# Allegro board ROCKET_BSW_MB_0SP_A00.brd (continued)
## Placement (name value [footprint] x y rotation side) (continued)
U2601  NCT7718W-GP  [MSOP8-1H44]  93.66 67.01 180 bottom
U2701  ALC3234-CG-GP  [QFN48J6-G465H40]  140.48 89.78 180 bottom
U2901  2N7002KDW-GP  [SOT-363H44]  149.73 87.56 180 bottom
U3301  RTS5176E-GRT-GP  [QFN24-G2D5H40-U]  14.1 40.77 0 bottom
U3601  G524B2T11U-GP  [SOT-23-5H58]  21.78 54.6 0 bottom
U4001  APL3523AQBI-TRG-GP  [SON14J3020-G2610H32]  147.06 47.31 270 bottom
U4016  APL3523AQBI-TRG-GP  [SON14J3020-G2610H32]  45.31 12.12 270 bottom
U5501  RT9724GB-GP  [SOT-23-5H51]  66.68 80.65 90 bottom
U6301  KLMBG4GEND-B031-GP  [BGA153G115130-1H40]  105.26 93.07 90 bottom
U6901  LNG2DMTR-GP  [LGA12G2H40]  56.62 91.47 270 top
USB1  SKT-USB13-262-GP  [SKT-USB13-160161]  5.39 54.5 90 bottom
WLAN1  SKT-NGFF75P-142-GP-U  [NFSA0-S6705-TP20]  175.1 85.5 90 bottom
X1601  XTAL-19D2MHZ-21-GP  [OSC-3225-4P-4H32]  53.97 46.22 270 bottom
X1802  XTAL-32D768KHZ-6-GP  [SMD-OSC2H56]  50.15 50.11 180 bottom

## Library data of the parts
AFTP2901-AFTP2904 AFTP2906-AFTP2909 AFTP3401-AFTP3404 AFTP4201-AFTP4203 AFTP4301-AFTP4305 AFTP5402 AFTP6101 AFTP6102 AFTP6104 AFTP6105 AFTP6110 AFTP6111 AFTP6113 AFTP6201-AFTP6218 AFTP6220-AFTP6233 = AFTE14P-75: tolerance: ZZ.AFT14.101
BATT1 = 88231-1001-LP: tolerance: 20.F1240.010
C1001-C1008 C1013 C1015-C1026 C1028 C1032-C1039 C1047 C1049 C1050 C1056 C1057 C1101-C1117 C1121 C1125-C1134 C1137 C1138 C1143 C1144 C1147-C1150 C1209-C1212 C1214-C1217 C1802 C1803 C2443 C2444 C2703 C2704 C2901 C3308 C3309 C3609 C5509 C6301 PC1044 PC4604 PC4807 PC5000 PC5007 PC5015 PC5110 PC5111 PC5221 PC5225 PC5301 PC5306 PC5401 = C402H22: tolerance: 78.10523.5FL
C1027 C1029 C1030 C6302 C6304 = C402-TO0D2H26: tolerance: 78.47510.5FL
C1201 C1208 C1213 C1810 C1811 C2417 C2428-C2432 C2436 C2438-C2442 C2445-C2447 C2501 C2505 C2601 C2606 C2612 C2707 C2709 C2710 C2717 C2719-C2721 C3301 C3302 C3306 C3606 C3608 C4002 C4046 C4050 C4051 C5508 C6102 C6104 C6303 C6305 C6504 C6505 C6702 C6902 EC4001-EC4004 EC4006 PC4507 PC4508 PC4513 PC4518 PC4530 PC4531 PC4614 PC4615 PC4617-PC4620 PC4803 PC4809 PC4814 PC4823 PC4834 PC4839 PC5001 PC5003 PC5102 PC5116 PC5118-PC5120 PC5138 PC5326 PC5427 = C402H22: tolerance: 78.10421.2FL
C1202 = C402H25: tolerance: 78.R20A4.L0L
C1203 C1206 C1219 C1221 C1222 C2502 C2602 C2702 C2712-C2714 C2902 C2907 C2908 C4003 C4005 C4011 C4012 C4037-C4039 C4042 C6901 PC5014 PC5016 PC5115 PC5219 PC5220 PC5402 = C603H38: tolerance: 78.10610.5BL
C1204 C1205 C1207 C1220 C1223 C6103 PC1031 PC1043 PC1045 PC1046 = C402-TO0D2H28: tolerance: 78.10610.5FL
C1601 C1602 = C402H22: tolerance: 78.3R374.1FL
C1801 = C402H22: tolerance: 78.22044.1FL
C1806 C1807 = C402H22: tolerance: 78.3R974.1FL
C1910 C2401 C2723 EC1103 EC1104 EC1106-EC1108 EC2708 EC2709 EC5505 EC5506 PC5017 PC5222 = C402H22: tolerance: 78.22034.1FL
C1915 C1916 C3505 C3506 C5501 C5505-C5507 C5510 C5513 C5701-C5708 = C402H22: tolerance: 78.10421.2FL; signal model: C402H22_SCD1U16V2KX-3GP
C2414 C2416 C2433 C2705 PC4524 PC4611 PC4808 PC5009 PC5113 = C603H36: tolerance: 78.22523.5BL
C2604 C4004 PC4601 PC4608 PC4804 PC4805 = C402H22: tolerance: 78.47124.2FL
C2605 PC4606 PC4819 = C402H22: tolerance: 78.22224.2FL
C2613 EC2905-EC2908 EC6403 EC6405 EC6502 PC4422 PC4602 PC4607 PC4810 PC4818 = C402H22: tolerance: 78.10134.1FL
C2701 C2706 C2708 C2711 C2715 C2716 C2718 C3304 C3307 C5511 C5512 C5514 PC4535 = C603H36: tolerance: 78.47520.5BL
C3303 = C402H22: tolerance: 78.10321.2FL
C3305 = C603H38: tolerance: 78.10620.5BL
C3310 = C402H22: tolerance: 78.10423.2FL
C3508-C3511 = C402H22: tolerance: 78.1R074.1FL
C3601 C3602 PC4509-PC4512 PC4514-PC4517 PC4527 PC5005 PC5010-PC5013 PC5101 PC5103-PC5105 PC5114 = C805H58: tolerance: 78.22610.51L
C4001 C5503 EC1001 EC1002 EC1004 EC1005 EC1007 EC1101 EC1102 EC1105 EC1201-EC1206 EC2901-EC2904 PC4525 PC4526 PC4603 PC4605 PC4612 PC4812 PC4815 = C402H22: tolerance: 78.10224.2FL
C4041 C4043 PC5002 PC5112 = C402H22: tolerance: 78.33124.2FL
C5006 C5504 EC2703-EC2707 EC2710 EC4303 EC4304 EC4306 EC4402 EC4403 EC5501-EC5503 EC5701 PC4302 PC4402 PC4420 PC4421 PC4423 PC4424 PC4501 PC4506 PC4521 PC4522 PC4534 PC4538 PC5117 = C402H22: tolerance: 78.10422.5FL
C5502 PC4408 PC4520 PC5004 PC5008 = C805H54: tolerance: 78.47522.51L
C6701 = C402H22: tolerance: 78.47321.2FL
CPU1 = BGA1170M2725H57: tolerance: 071.BRASW.000U
D1901 = SOT23-2D4-312H44: tolerance: 83.00016.K11
D2701 D5501 D5502 = SOT23-2D4-312H48: tolerance: 75.00054.E7D
D4001 = SOT23-2D4-312H44: tolerance: 83.00016.P11
D4301-D4303 PD4303 = SOT23-2D4-312H44: tolerance: 75.00099.O7D
D5701 = SOT23-2D4-312H44: tolerance: 83.00056.Y11
DB1 = PAD-87212-1002N: tolerance: ZZ.00PAD.GV1
DCIN1 = 50224-0060N-W01: tolerance: 20.F1639.006
EC502-EC504 EC1808-EC1814 EC2401-EC2403 EC4005 EC6504 EC6505 = SOD882-10D6-1H20: tolerance: 83.05725.0A0
EC1003 EC1006 EC4308-EC4313 EC4401 PC4303-PC4305 PC4412 PC4425 PC4610 PC4806 PC5107 = C402H22: tolerance: 78.10324.2FL
EC1801-EC1803 EC4301 EC4302 EC4305 EC4307 EC6506 = C402H22: tolerance: 78.10034.1FL
EC2501-EC2503 EC6501 EC6503 = C402H22: tolerance: 78.4R7B4.1FL
EC2601 EC2602 EC5510 PC5405 = C402H22: tolerance: 78.33034.1FL
EC3301-EC3306 = SOD882-10D6-1H20: tolerance: 83.05123.AA0
EC3307 = C402H22: tolerance: 78.5R074.1FL
EC4701 EC4801 PC4401 PC4409 PC4419 = C603H36: tolerance: 78.10424.2BL
EC5507 = C402H22: tolerance: 78.6R074.1FL
EC6427 EC6428 = SOD-523-2H26: tolerance: 83.0005V.0AF
EL4301-EL4304 PR4422 PR4426 PR4504 PR4510 PR4511 PR4514 PR4605 PR4640 PR4644 PR4652 PR4658 PR4660 PR4807-PR4809 PR4834 PR4836 PR5004 PR5007 PR5009 PR5066 PR5102 PR5105 PR5107 PR5114 PR5117 PR5125 PR5201 PR5417 R1203 R1207 R1615 R1809 R1810 R1821 R1827 R1833 R1835 R1844 R1901 R1903 R1906 R1907 R2413-R2415 R2417 R2424 R2425 R2439 R2440 R2443 R2461 R2486-R2488 R2495 R2496 R2511 R2512 R2521-R2526 R2528 R2530 R2532 R2601 R2603 R2609 R2613 R2701 R2705 R2708 R2711 R2713 R2714 R2716 R3302 R3309 R3311 R4001 R4003 R4010 R4015 R4017 R4019 R4029 R4055 R4064 R4301 R5501-R5503 R5518 R5702 R6327 R6328 R6501 R6502 R6508 R6509 R6515 = 0R0402-PAD: tolerance: ZZ.R0402.ZZZ
EU3501 = DFN10G2510H22: tolerance: 075.01043.0073
EU3505 = SOT-6H58: tolerance: 075.09904.0A7C
F5501 = POLYSW-4633-UH43: tolerance: 69.50007.A31
F5502 F5701 = POLYSW-2114H30: tolerance: 69.48001.081
G1801 = CON2O-U: tolerance: ZZ.CON2O.XXX
H1 = HOLE354R237: tolerance: ZZ.PAD01.041
H2 = HOLE256R142-OG: tolerance: ZZ.00PAD.6U1
H4 H9 = HOLE335R197: tolerance: ZZ.00PAD.7L1
HDMI1 = SKT-HDMI23-188125-1-U1: tolerance: 022.10025.00F1
HS1-HS4 = STF237R117H67: tolerance: 34.4OX45.101
IOBD1 = 51540-04401-W01: tolerance: 20.K0678.044
KB1 = 50699-03041-001: tolerance: 20.K0700.030
LCD1 = 51540-04001-W01: tolerance: 20.K0678.040
LED1 = 51575-00401-W01: tolerance: 20.K0800.004
LIDSW1 = SOT23-2D8-123H52: tolerance: 74.05712.0BB
PC1009-PC1012 PC1014 PC1040-PC1042 PC1048 PC1051-PC1055 PC1058-PC1080 PC1118-PC1120 PC1122-PC1124 PC4706-PC4708 PC4820-PC4822 PC5018 PC5019 PC5223 PC5224 = C603H40: tolerance: 78.22610.5BL
PC4301 = C805H58: tolerance: 78.10594.41L
PC4306 PC4406 PC4415-PC4418 PC4426 PC4502-PC4505 PC4519 PC4523 PC4528 PC4529 PC4702 PC4705 PC4801 PC4811 PC5106 PC5108 PC5404 PC5407 = C805H56: tolerance: 78.10622.51L
PC4403 PC4404 PC4407 PC4427 PC4431 PC4434 = C603H36: tolerance: 78.10522.5BL
PC4410 = C603H36: tolerance: 78.47422.5BL
PC4411 = C402H22: tolerance: 78.47322.2FL
PC4413 = C603H36: tolerance: 78.33224.2BL
PC4433 = C402H22: tolerance: 78.47420.5FL
PC4609 PC4813 = C603H40: tolerance: 78.22422.2BL
PC4613 = C402H22: tolerance: 78.22322.2FL
PC4710 PC4817 = C603: tolerance: 78.33124.2BL
PC4802 = C402H24: tolerance: 78.56124.2FL
PC4816 = C402H22: tolerance: 78.15322.2FL
PD4301 = DO214AAAKH97: tolerance: 83.P6SMB.JAG
PD4302 = SOD123FLAKH40: tolerance: 83.SMF18.0AH
PD4401 = SOD323AKH38: tolerance: 83.2R004.08F
PD4404 = SOD323AKH42: tolerance: 83.04148.D1H
PG4402-PG4405 PG4407-PG4411 PG4517 PG4519 PG4521 PG4523 PG4525 PG4527-PG4529 PG4532-PG4535 PG4537-PG4542 PG4544-PG4546 PG4707 PG4709 PG4801 PG4802 PG5001-PG5005 PG5101-PG5109 PG5117 PG5118 PG5207-PG5210 PG5408 PG5409 = GAP-CLOSE-PWR-3: tolerance: ZZ.CLOSE.001
PL4401 = L7066-1830-UH119: tolerance: 68.2R21A.20B
PL4501 PL4502 = L4947-1015H119: tolerance: 68.1R550.20C
PL4701 = L6965-1330-UH119: tolerance: 68.R3610.10R
PL4801 = L7066-1830-UH119: tolerance: 68.R2210.10V
PL5001 PL5101 = L4947-1115H119: tolerance: 68.1R010.20R
PL5002 PL5201 = L3030-3009H60: tolerance: 68.2R21G.10N
PQ4301 Q1811 Q5703 Q5705 Q6301 = SOT23DGS2D4H48: tolerance: 84.05067.031
PQ4302 Q2601 Q5501 Q5503 = SOT23CBE2D4H44: tolerance: 84.T3904.H11
PQ4304 = SC70-2D2-312H44: tolerance: 84.00024.A1K
PQ4305 = SC70-2D2-312H44: tolerance: 84.00024.01K
PQ4309 PQ4414 Q801 Q1901 Q2402 Q2403 Q2502 Q2603 Q2901 Q3301 Q4015 Q4017 Q4020 Q5506 Q5707 Q6502 = SOT23DGS2D4H44: tolerance: 84.2N702.J31
PQ4402 PQ4407 PQ4408 PQ4410 Q1622 Q1801 Q1810 Q1813 Q2604 Q4001 Q4014 Q4016 Q5701 Q6507 U2901 = SOT-363H44: tolerance: 84.2N702.A3F
PQ4409 Q2401 = SOT23CBE2D4H44: tolerance: 84.T3906.E11
PR4168 = R402H16: tolerance: 64.40215.6DL
PR4302 = R402H16: tolerance: 64.15025.6DL
PR4303 PR4638 PR4649 PR4813 PR5012 PR5218 R806 R808-R810 R812 R818 R819 R1808 R1820 R1823 R1830 R1843 R1850 R1856 R1858 R1902 R1904 R2400 R2403 R2405 R2407 R2420 R2421 R2426-R2428 R2436 R2462 R2464 R2471 R2475 R2490 R2712 R2919 R2920 R3307 R4020 R4024 R4031 R5517 R5705 R6326 R6329-R6338 R6902 R6905 = R402H16: tolerance: 63.10334.1DL
PR4306 R1610 R1616 R1620-R1623 R1813 R1842 R5516 R5521 R5526 R5527 R6511 R6512 = R402H16: tolerance: 63.22234.1DL
PR4307 R2401 R2416 R2418 R2517 = R402H16: tolerance: 63.33034.1DL
PR4309 = R603H22: tolerance: 63.24434.15L
PR4310 = R603H22: tolerance: 63.47333.15L
PR4311 PR4403 PR4417 PR4419 PR4425 PR4428 PR4430 PR4434 PR4438 PR4469 PR4474 PR4534 PR5013 R803 R804 R1531 R1532 R1536 R1826 R1828 R1861 R2410 R2434 R2442 R2702 R2704 R2905 R2918 R3308 R3605 R4008 R4011 R4014 R4053 R5505-R5508 R5522 R5703 R6701 = R402H16: tolerance: 63.10434.1DL
PR4312 PR4607 PR4827 PR5008 R1525 R1841 R1864 R2419 R2468 R2493 R2501 R2717 R2719 R2921 R2922 R4047 R4048 R6503 R6516 = R402H16: tolerance: 63.10234.1DL
PR4316 = R1206H28: tolerance: 63.33232.11L
PR4401 PR4435 PR4473 PR4643 PR4833 R1503 R1504 R1506 R1508 R1513-R1515 R1517 R1520 R1523 R1524 R1526 R1527 R1529 R1535 R1537 R2430 = R402H16: tolerance: 64.10025.6DL
PR4402 PR4416 = R3720H40: tolerance: 64.R0105.7FL
PR4404 = R805H24: tolerance: 63.30231.16L
PR4405 R2915 = R402H16: tolerance: 63.47434.1DL
PR4406 PR4418 PR4448 PR4465 PR4466 PR4468 PR4475 PR4476 PR5106 PR5315 R1611 R1617-R1619 R1811 R1845 R1905 R2404 R2411 R2494 R2513 R2514 R2602 R2607 R4004 R4016 R4021 R4022 R4065 R5524 R6106-R6108 R6406 R6409 R6510 R6513 R6514 R6518 R6901 R6903 R6906 R6907 = R402H16: tolerance: 63.R0034.1DL
PR4407 = R402H16: tolerance: 64.28735.6DL
PR4408 = R805H24: tolerance: 63.10031.16L
PR4409 PR4501 PR4502 PR4532 PR5001 PR5101 R2409 R2703 R2706 R2906 R2907 R2909 R2911 R5401 R6105 R6324 R6325 = 0R0603-PAD: tolerance: ZZ.R0603.ZZZ
PR4410 = R402H16: tolerance: 64.6R805.6DL
PR4411 = R402H16: tolerance: 64.10235.6DL
PR4412 PR4415 = R402H16: tolerance: 64.33015.6DL
PR4413 = R402H16: tolerance: 64.16935.L0L
PR4414 = R402H16: tolerance: 63.33534.1DL
PR4420 = R402H16: tolerance: 64.7R505.6DL
PR4421 PR4454 PR5039 R2908 R2910 = R402H14: tolerance: 64.10R05.6DL
PR4423 = R402H16: tolerance: 64.59025.6DL
PR4424 = R402H16: tolerance: 64.84515.6DL
PR4427 = R402H16: tolerance: 64.78725.6DL
PR4429 = R402H16: tolerance: 64.30935.6DL
PR4431 = R402H16: tolerance: 64.47025.6DL
PR4432 PR4433 PR4436 = R402H16: tolerance: 64.12035.6DL
PR4437 = R402H16: tolerance: 64.16035.6DL
PR4446 R2707 = R402H16: tolerance: 64.20025.6DL
PR4464 = R402H16: tolerance: 63.68434.1DL
PR4467 PR4516 PR4518 PR5003 R813 = R402H16: tolerance: 63.10534.1DL
PR4470 PR4472 PR4614 PR4830 PR5005 PR5211 R2438 = R402H16: tolerance: 64.10035.6DL
PR4506 PR4507 PR4512 PR4515 PR4604 PR4803 = R402H16: tolerance: 64.10015.6DL
PR4513 PR4517 = R402H16: tolerance: 64.20035.L0L
PR4601 PR4602 PR4804 PR4805 R1824 = R402H16: tolerance: 64.20005.6DL
PR4603 PR4801 = R402H16: tolerance: 64.47R05.6DL
PR4606 PR4825 PR5014 = R402H16: tolerance: 64.75025.6DL
PR4609 PR4802 = R402H16: tolerance: 64.56035.6DL
PR4610 PR4835 = R402H16: tolerance: 64.15015.6DL
PR4612 PR4823 R2408 = R603H22: tolerance: 64.2R205.55L
PR4613 PR4824 R6309 = R402H14: tolerance: 63.10034.1DL
PR4615 PR4828 = R402H16: tolerance: 64.14725.6DL
PR4616 PR4831 = R402H16: tolerance: 64.13015.6DL
PR4617 = R603H22: tolerance: 64.21535.55L
PR4619 = R402H16: tolerance: 64.46425.6DL
PR4620 PR4817 = R603H22: tolerance: 63.2R233.15L
PR4621 PR4816 = R402H16: tolerance: 64.56R25.6D1
PR4635 PR4814 PR5202 R1839 R1860 R1862 R1863 R2492 = R402H16: tolerance: 63.20334.1DL
PR4637 PR4818 = R603H22: tolerance: 63.1R033.15L
PR4645 PR4875 = R402H16: tolerance: 63.20134.1DL
PR4648 PR4661 PR4810 PR4812 = NTC-402H24-U: tolerance: 69.60028.041
PR4663 PR4854 R1636 = R402H16: tolerance: 64.49R95.6DL
PR4665 PR4843 = R402H16: tolerance: 64.30005.6DL
PR4669 PR4855 = R402H16: tolerance: 63.20034.1DL
PR4676 PR4678 PR5006 R814 R1639 R1848 R1849 R1851 R1852 R1859 R1873-R1875 = R402H14: tolerance: 64.10005.6DL
PR4684 = R402H16: tolerance: 64.31625.6DL
PR4704 PR4847 = R805H24: tolerance: 64.2R205.16L
PR4819 = R402H16: tolerance: 64.34025.6DL
PR4820 = R402H16: tolerance: 64.36015.6DL
PR4821 = R402H16: tolerance: 64.41225.6DL
PR4822 = R402H16: tolerance: 64.48725.6DL
PR4832 = R603H22: tolerance: 64.20035.55L
PR5002 = R402H16: tolerance: 64.47035.6DL
PR5010 = R402H16: tolerance: 64.53625.6DL
PR5011 PR5213 = R402H16: tolerance: 64.49925.6DL
PR5103 = R402H16: tolerance: 64.42225.6DL
PR5104 = R402H16: tolerance: 64.33225.6DL
PR5401 R2437 = R402H16: tolerance: 63.47334.1DL
PR5419 = R402H16: tolerance: 64.73215.6DL
PR5420 = R402H16: tolerance: 64.13325.6DL
PT4701 PT4801 = CT3528H79: tolerance: 77.23371.34L
PT4702 = CT7343H83: tolerance: 79.33612.20L
PU4301 PU4402 PU4403 = PPAK-8P-2H45: tolerance: 84.07121.037
PU4404 = QFN20G3D5-G2D15H40: tolerance: 74.24727.A73
PU4405 = DFN8F3-G2PH26: tolerance: 84.08K11.030
PU4407 = SC70-6H44: tolerance: 74.00199.07P
PU4502 = QFN20Z3-G1D1H36: tolerance: 074.08286.0043
PU4503 = QFN20Z3-G1D1H36: tolerance: 074.08286.0A43
PU4601 PU4802 = LFQFN28J4-G2D7-UH40: tolerance: 074.81201.0073
PU4701 PU4801 = PPAK-8P-G5324H44-COLAY: tolerance: ZZ.00215.037
PU5001 PU5101 = QFN20Z3-G1D1H36: tolerance: 074.08286.0B43
PU5002 PU5204 = DFN8G2-G1711H26: tolerance: 74.00232.033
PU5102 = MSOP10-G2D5H44: tolerance: 74.05338.079
PU5301 = SOT-23-5H52: tolerance: 74.01339.B3F
PU5402 = SOIC8-G3530H63: tolerance: 74.05930.03D
Q1606 Q1814 = SOT-363H44: tolerance: 075.00138.0A7C
Q1812 = SOT23DGS2D4H35: tolerance: 84.3K329.031
Q2404 Q6503 Q6504 = SOT23DGS2D4H48: tolerance: 84.02130.031
Q2501 = SOT-23-9H44: tolerance: 75.00040.07D
Q6403 Q6404 = SOT23CBE2D4H44: tolerance: 84.00144.N11
Q6501 = SOT23CBE2D8H56: tolerance: 84.02144.011
R504 R508 = R402H16: tolerance: 64.18205.6DL
R801 R802 R1642 R1930 R1931 = R402H16: tolerance: 64.40205.6DL
R807 R1807 R2435 R3303 R3502 R3503 R3509 R3512 R6101-R6104 = 0R0402-PAD: tolerance: ZZ.R0402.ZZZ; signal model: R402H16_0R2J-2-GP
R815 R1217-R1237 R1240-R1242 R1244-R1246 = R402H16: tolerance: 64.80R65.6DL
R817 R5714-R5717 = R402H16: tolerance: 64.15005.6DL
R1202 R1204-R1206 R1519 R1522 = R402H16: tolerance: 64.47015.6DL
R1208-R1211 = R402H16: tolerance: 64.24005.6DL
R1601 = R402H16: tolerance: 64.24915.6DL
R1603 = R402H16: tolerance: 64.20035.6DL
R1637 = R402H16: tolerance: 64.45R35.6DL
R1641 = R402H16: tolerance: 64.11305.6DL
R1802 R1803 R1909 = R402H16: tolerance: 63.33034.1DL; signal model: R402H16_33R2J-2-GP
R1816 R2505 = R402H16: tolerance: 63.10634.1DL
R1825 = R402H16: tolerance: 63.27234.1DL
R1910 R1911 R2529 R2531 R2536 R6312-R6322 = R402H14: tolerance: 63.10034.1DL; signal model: R402H14_10R2J-2-GP
R1926-R1929 R2718 = R402H16: tolerance: 64.75R05.6DL; signal model: R402H16_75R2F-2-GP
R2445 = R402H16: tolerance: 63.82234.1DL
R2489 R2491 = R402H16: tolerance: 63.33434.1DL
R2516 R2527 = R402H16: tolerance: 63.R0034.1DL; signal model: R402H16_0R2J-2-GP
R2604 R2612 = NTC-603H38: tolerance: 69.60035.041
R2605 = R402H16: tolerance: 64.18725.6DL
R2606 = R402H16: tolerance: 64.20015.6DL
R2608 R2614 = R402H16: tolerance: 64.24925.6DL
R2615 = R402H16: tolerance: 63.20234.1DL
R2709 R4005 = R402H16: tolerance: 63.20434.1DL
R2901-R2904 = L1608-UH38: tolerance: 68.00206.021
R2912 R2913 R4002 R6504 = R402H16: tolerance: 63.47234.1DL
R2914 R2923 = R603H22: tolerance: 63.R0033.15L
R3304 = R402H16: tolerance: 64.62015.6DL
R4027 = R603H22: tolerance: 64.22005.55L
R6310 R6311 = R603H22: tolerance: 63.00000.00L
R6407 = R402H16: tolerance: 64.49905.6DL
R6408 = R402H16: tolerance: 63.33134.1DL
R6505 R6506 = R402H16: tolerance: 63.22134.1DL
RAM1-RAM4 = BGA96D0914H48: tolerance: 72.41K26.B0U
RN801 RN1607 RN1801 RN1803 RN1901 RN1902 RN2402 RN4001 RN5704 RN6503 = ARES2H18: tolerance: 66.10336.04L
RN803 RN1601 RN1603 RN2401 RN2601 RN2901 RN5701 RN6901 = ARES2H16: tolerance: 66.22236.04L
RN1501 RN2403 = SMD-ARES4: tolerance: 66.10436.04L
RN1502 = SMD-ARES4H18: tolerance: 66.47236.04L
RN1802 = ARES8-CN24H22: tolerance: 66.R0036.A8L; signal model: ARES8-CN24H22_SRN0J-7-GP-U
RN1805 = ARES8-CN24H22: tolerance: 66.51036.A8L
RN1806 = SMD-ARES4H18: tolerance: 66.51036.04L
RN2501 = ARES8-CN24H20: tolerance: 66.47236.08L
RN2701 RN4501 = SMD-ARES4H20: tolerance: 66.R0036.04L
RN4301 RN5501 = ARES8-CN24H20: tolerance: 66.10136.A8L
RN5502 RN6502 = SMD-ARES4H18: tolerance: 66.33036.04L
RN5702 RN5703 = ARES8-CN24H20: tolerance: 66.47136.08L
RTC1 = 50224-0020N-W02: tolerance: 20.F1639.002
SD1 = PTFBT4-09GLBS1NN4H2: tolerance: 062.10002.0081
SPK1 = 50224-0040N-001: tolerance: 20.F1639.004
SPR1-SPR3 = SPR5128H111: tolerance: 34.4YW18.001
SPR4-SPR6 = SPR5432H83: tolerance: 34.34S02.002
SSKT1 = G6179HT0321-001: tolerance: 62.10089.011
TP501 TP502 TP801 TP802 TP805-TP814 TP901 TP902 TP1608-TP1622 TP1801-TP1803 TP2101 TP2403 TP2407-TP2409 TP2702 TP5401 TP5501 TP6101 TP6102 TP6301-TP6304 = TPAD14-OP: tolerance: ZZ.PAD14.001
TPAD1 = 51574-0084N-W01: tolerance: 020.K0151.0008
TR3301 = L125100-4P-4H24: tolerance: 68.00396.001
TR3503 TR5501 TR6601 = L125100-4P-4H28: tolerance: 68.01012.20B
U2401 = LQFP128H63: tolerance: 071.00985.000G
U2404 = SC70-6H44: tolerance: 73.02129.02J
U2501 = SOIC8-1H86: tolerance: 72.25Q64.S01
U2503 = DFN10G3-G265175H32: tolerance: 073.03950.0003
U2601 = MSOP8-1H44: tolerance: 74.07718.0B9
U2701 = QFN48J6-G465H40: tolerance: 71.03234.003
U3301 = QFN24-G2D5H40-U: tolerance: 71.05176.A03
U3601 = SOT-23-5H58: tolerance: 074.00524.0C9F
U4001 U4016 = SON14J3020-G2610H32: tolerance: 74.03523.A73
U5501 = SOT-23-5H51: tolerance: 74.09724.09F
U6301 = BGA153G115130-1H40: tolerance: 072.KMBG4.0C0U
U6901 = LGA12G2H40: tolerance: 074.LNG2D.00BZ
USB1 = SKT-USB13-160161: tolerance: 022.10005.02V1
WLAN1 = NFSA0-S6705-TP20: tolerance: 062.10003.0001
X1601 = OSC-3225-4P-4H32: tolerance: 082.30001.0061
X1802 = SMD-OSC2H56: tolerance: 82.30001.B21

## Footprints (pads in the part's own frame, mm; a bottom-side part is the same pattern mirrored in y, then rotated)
0R0402-PAD
  custom 0.14x0.14 smd: 1(0,0.445) 2(0,-0.445)
0R0603-PAD
  custom 0.216x0.216 smd: 1(0,0.851) 2(0,-0.673)
50224-0020N-W02
  rect 0.61x1.549 smd: 1(-0.5,3.876) 2(0.5,3.876)
  rect 1.194x1.803 smd: 3(-1.797,0) 4(1.797,0)
50224-0040N-001
  rect 0.61x1.549 smd: 1(-1.5,3.875) 2(-0.5,3.875) 3(0.5,3.875) 4(1.5,3.875)
  rect 1.194x1.803 smd: 5(-2.797,0) 6(2.797,0)
50224-0060N-W01
  rect 0.406x1.549 smd: 1(-2.5,3.875) 2(-1.5,3.875) 3(-0.5,3.875) 4(0.5,3.875) 5(1.5,3.875) 6(2.5,3.875)
  rect 1.194x1.803 smd: 7(-3.8,0) 8(3.8,0)
50699-03041-001
  rect 0.406x0.813 smd: 1(-11.6,3.3) 2(-10.8,3.3) 3(-10,3.3) 4(-9.2,3.3) 5(-8.4,3.3) 6(-7.6,3.3) 7(-6.8,3.3) 8(-6,3.3) 9(-5.2,3.3) 10(-4.4,3.3) 11(-3.6,3.3) 12(-2.8,3.3) 13(-2,3.3) 14(-1.2,3.3) 15(-0.4,3.3) 16(0.4,3.3) 17(1.2,3.3) 18(2,3.3) 19(2.8,3.3) 20(3.6,3.3) 21(4.4,3.3) 22(5.2,3.3) 23(6,3.3) 24(6.8,3.3) 25(7.6,3.3) 26(8.4,3.3) 27(9.2,3.3) 28(10,3.3) 29(10.8,3.3) 30(11.6,3.3)
  rect 0.559x1.295 smd: 31(-13.075,0) 32(13.075,0)
51540-04001-W01
  rect 0.305x0.838 smd: 1(-9.75,3.175) 2(-9.25,3.175) 3(-8.75,3.175) 4(-8.25,3.175) 5(-7.75,3.175) 6(-7.25,3.175) 7(-6.75,3.175) 8(-6.25,3.175) 9(-5.75,3.175) 10(-5.25,3.175) 11(-4.75,3.175) 12(-4.25,3.175) 13(-3.75,3.175) 14(-3.25,3.175) 15(-2.75,3.175) 16(-2.25,3.175) 17(-1.75,3.175) 18(-1.25,3.175) 19(-0.75,3.175) 20(-0.25,3.175) 21(0.25,3.175) 22(0.75,3.175) 23(1.25,3.175) 24(1.75,3.175) 25(2.25,3.175) 26(2.75,3.175) 27(3.25,3.175) 28(3.75,3.175) 29(4.25,3.175) 30(4.75,3.175) 31(5.25,3.175) 32(5.75,3.175) 33(6.25,3.175) 34(6.75,3.175) 35(7.25,3.175) 36(7.75,3.175) 37(8.25,3.175) 38(8.75,3.175) 39(9.25,3.175) 40(9.75,3.175)
  rect 0.813x2.007 smd: 41(-11.45,0) 42(11.45,0)
51540-04401-W01
  rect 0.305x0.838 smd: 1(-10.75,3.175) 2(-10.25,3.175) 3(-9.75,3.175) 4(-9.25,3.175) 5(-8.75,3.175) 6(-8.25,3.175) 7(-7.75,3.175) 8(-7.25,3.175) 9(-6.75,3.175) 10(-6.25,3.175) 11(-5.75,3.175) 12(-5.25,3.175) 13(-4.75,3.175) 14(-4.25,3.175) 15(-3.75,3.175) 16(-3.25,3.175) 17(-2.75,3.175) 18(-2.25,3.175) 19(-1.75,3.175) 20(-1.25,3.175) 21(-0.75,3.175) 22(-0.25,3.175) 23(0.25,3.175) 24(0.75,3.175) 25(1.25,3.175) 26(1.75,3.175) 27(2.25,3.175) 28(2.75,3.175) 29(3.25,3.175) 30(3.75,3.175) 31(4.25,3.175) 32(4.75,3.175) 33(5.25,3.175) 34(5.75,3.175) 35(6.25,3.175) 36(6.75,3.175) 37(7.25,3.175) 38(7.75,3.175) 39(8.25,3.175) 40(8.75,3.175) 41(9.25,3.175) 42(9.75,3.175) 43(10.25,3.175) 44(10.75,3.175)
  rect 0.813x2.007 smd: 45(-12.45,0) 46(12.45,0)
51574-0084N-W01
  rect 0.305x1.194 smd: 1(-3.5,3.3) 2(-2.5,3.3) 3(-1.5,3.3) 4(-0.5,3.3) 5(0.5,3.3) 6(1.5,3.3) 7(2.5,3.3) 8(3.5,3.3)
  rect 0.406x0.813 smd: 9(-5.185,0) 10(5.185,0)
51575-00401-W01
  rect 0.406x0.838 smd: 1(-1.5,3.175) 2(-0.5,3.175) 3(0.5,3.175) 4(1.5,3.175)
  rect 0.813x2.007 smd: 5(-3.7,0) 6(3.7,0)
88231-1001-LP
  rect 0.813x1.905 smd: 1(-5.625,4.878) 2(-4.375,4.878) 3(-3.125,4.878) 4(-1.875,4.878) 5(-0.625,4.878) 6(0.625,4.878) 7(1.875,4.878) 8(3.125,4.878) 9(4.375,4.878) 10(5.625,4.878)
  rect 1.295x3.353 smd: 11(-8.473,0) 12(8.473,0)
AFTE14P-75
  round 0.356 smd: 1(0,0)
ARES2H16
  rect 0.356x0.66 smd: 1(-0.325,-0.599) 2(0.325,-0.599) 3(0.325,0.599) 4(-0.325,0.599)
ARES2H18
  rect 0.356x0.66 smd: 1(-0.325,-0.599) 2(0.325,-0.599) 3(0.325,0.599) 4(-0.325,0.599)
ARES8-CN24H20
  rect 0.61x0.66 smd: 1(-0.9,-0.486) 4(0.9,-0.486) 5(0.9,0.486) 8(-0.9,0.486)
  rect 0.305x0.66 smd: 2(-0.25,-0.486) 3(0.25,-0.486) 6(0.25,0.486) 7(-0.25,0.486)
ARES8-CN24H22
  rect 0.61x0.66 smd: 1(-0.9,-0.486) 4(0.9,-0.486) 5(0.9,0.486) 8(-0.9,0.486)
  rect 0.305x0.66 smd: 2(-0.25,-0.486) 3(0.25,-0.486) 6(0.25,0.486) 7(-0.25,0.486)
BGA96D0914H48
  round 0.356 smd: A1(-3.2,6) A2(-2.4,6) A3(-1.6,6) A7(1.6,6) A8(2.4,6) A9(3.2,6) B1(-3.2,5.2) B2(-2.4,5.2) B3(-1.6,5.2) B7(1.6,5.2) B8(2.4,5.2) B9(3.2,5.2) C1(-3.2,4.4) C2(-2.4,4.4) C3(-1.6,4.4) C7(1.6,4.4) C8(2.4,4.4) C9(3.2,4.4) D1(-3.2,3.6) D2(-2.4,3.6) D3(-1.6,3.6) D7(1.6,3.6) D8(2.4,3.6) D9(3.2,3.6) E1(-3.2,2.8) E2(-2.4,2.8) E3(-1.6,2.8) E7(1.6,2.8) E8(2.4,2.8) E9(3.2,2.8) F1(-3.2,2) F2(-2.4,2) F3(-1.6,2) F7(1.6,2) F8(2.4,2) F9(3.2,2) G1(-3.2,1.2) G2(-2.4,1.2) G3(-1.6,1.2) G7(1.6,1.2) G8(2.4,1.2) G9(3.2,1.2) H1(-3.2,0.4) H2(-2.4,0.4) H3(-1.6,0.4) H7(1.6,0.4) H8(2.4,0.4) H9(3.2,0.4) J1(-3.2,-0.4) J2(-2.4,-0.4) J3(-1.6,-0.4) J7(1.6,-0.4) J8(2.4,-0.4) J9(3.2,-0.4) K1(-3.2,-1.2) K2(-2.4,-1.2) K3(-1.6,-1.2) K7(1.6,-1.2) K8(2.4,-1.2) K9(3.2,-1.2) L1(-3.2,-2) L2(-2.4,-2) L3(-1.6,-2) L7(1.6,-2) L8(2.4,-2) L9(3.2,-2) M1(-3.2,-2.8) M2(-2.4,-2.8) M3(-1.6,-2.8) M7(1.6,-2.8) M8(2.4,-2.8) M9(3.2,-2.8) N1(-3.2,-3.6) N2(-2.4,-3.6) N3(-1.6,-3.6) N7(1.6,-3.6) N8(2.4,-3.6) N9(3.2,-3.6) P1(-3.2,-4.4) P2(-2.4,-4.4) P3(-1.6,-4.4) P7(1.6,-4.4) P8(2.4,-4.4) P9(3.2,-4.4) R1(-3.2,-5.2) R2(-2.4,-5.2) R3(-1.6,-5.2) R7(1.6,-5.2) R8(2.4,-5.2) R9(3.2,-5.2) T1(-3.2,-6) T2(-2.4,-6) T3(-1.6,-6) T7(1.6,-6) T8(2.4,-6) T9(3.2,-6)
BGA153G115130-1H40
  oval 0.229x0.356 smd: A1(-3.25,3.25) A2(-2.75,3.25) A3(-2.25,3.25) A4(-1.75,3.25) A5(-1.25,3.25) A6(-0.75,3.25)
  round 0.356 smd: A7(-0.25,3.25) A8(0.25,3.25) A9(0.75,3.25) A10(1.25,3.25) A11(1.75,3.25) A12(2.25,3.25) A13(2.75,3.25) A14(3.25,3.25) B2(-2.75,2.75) B3(-2.25,2.75) B4(-1.75,2.75) B5(-1.25,2.75) B6(-0.75,2.75) B7(-0.25,2.75) B8(0.25,2.75) B9(0.75,2.75) B10(1.25,2.75) B11(1.75,2.75) B12(2.25,2.75) B13(2.75,2.75) B14(3.25,2.75) C2(-2.75,2.25) C3(-2.25,2.25) C4(-1.75,2.25) C5(-1.25,2.25) C6(-0.75,2.25) C7(-0.25,2.25) C8(0.25,2.25) C9(0.75,2.25) C10(1.25,2.25) C11(1.75,2.25) C12(2.25,2.25) C13(2.75,2.25) C14(3.25,2.25) D1(-3.25,1.75) D2(-2.75,1.75) D3(-2.25,1.75) D4(-1.75,1.75) D12(2.25,1.75) D13(2.75,1.75) D14(3.25,1.75) E1(-3.25,1.25) E2(-2.75,1.25) E3(-2.25,1.25) E5(-1.25,1.25) E6(-0.75,1.25) E7(-0.25,1.25) E8(0.25,1.25) E9(0.75,1.25) E10(1.25,1.25) E12(2.25,1.25) E13(2.75,1.25) E14(3.25,1.25) F1(-3.25,0.75) F2(-2.75,0.75) F3(-2.25,0.75) F5(-1.25,0.75) F10(1.25,0.75) F12(2.25,0.75) F13(2.75,0.75) F14(3.25,0.75) G1(-3.25,0.25) G2(-2.75,0.25) G3(-2.25,0.25) G5(-1.25,0.25) G10(1.25,0.25) G12(2.25,0.25) G13(2.75,0.25) G14(3.25,0.25) H1(-3.25,-0.25) H2(-2.75,-0.25) H3(-2.25,-0.25) H5(-1.25,-0.25) H10(1.25,-0.25) H12(2.25,-0.25) H13(2.75,-0.25) H14(3.25,-0.25) J1(-3.25,-0.75) J2(-2.75,-0.75) J3(-2.25,-0.75) J5(-1.25,-0.75) J10(1.25,-0.75) J12(2.25,-0.75) J13(2.75,-0.75) J14(3.25,-0.75) K1(-3.25,-1.25) K2(-2.75,-1.25) K3(-2.25,-1.25) K5(-1.25,-1.25) K6(-0.75,-1.25) K7(-0.25,-1.25) K8(0.25,-1.25) K9(0.75,-1.25) K10(1.25,-1.25) K12(2.25,-1.25) K13(2.75,-1.25) K14(3.25,-1.25) L1(-3.25,-1.75) L2(-2.75,-1.75) L3(-2.25,-1.75) L12(2.25,-1.75) L13(2.75,-1.75) L14(3.25,-1.75) M2(-2.75,-2.25) M3(-2.25,-2.25) M4(-1.75,-2.25) M5(-1.25,-2.25) M6(-0.75,-2.25) M7(-0.25,-2.25) M8(0.25,-2.25) M9(0.75,-2.25) M10(1.25,-2.25) M11(1.75,-2.25) M12(2.25,-2.25) M13(2.75,-2.25) M14(3.25,-2.25) N2(-2.75,-2.75) N3(-2.25,-2.75) N4(-1.75,-2.75) N5(-1.25,-2.75) N6(-0.75,-2.75) N7(-0.25,-2.75) N8(0.25,-2.75) N9(0.75,-2.75) N10(1.25,-2.75) N11(1.75,-2.75) N12(2.25,-2.75) N13(2.75,-2.75) N14(3.25,-2.75) P2(-2.75,-3.25) P3(-2.25,-3.25) P4(-1.75,-3.25) P5(-1.25,-3.25) P6(-0.75,-3.25) P7(-0.25,-3.25) P8(0.25,-3.25) P9(0.75,-3.25) P10(1.25,-3.25) P11(1.75,-3.25) P12(2.25,-3.25) P13(2.75,-3.25) P14(3.25,-3.25)
  oval 0.356x0.229 smd: B1(-3.25,2.75) C1(-3.25,2.25) M1(-3.25,-2.25) N1(-3.25,-2.75) P1(-3.25,-3.25)
BGA1170M2725H57
  round 0.508 smd: A3(11.951,-11.814) A52(-12.383,-11.814) B2(12.383,-11.383) B53(-12.814,-11.383) BH1(12.814,11.383) BH53(-12.814,11.383) BJ2(12.383,11.814) BJ52(-12.383,11.814) C1(12.814,-10.951)
  round 0.406 smd: A5(11.17,-11.814) A6(10.447,-11.814) A49(-10.992,-11.814) A51(-11.773,-11.814) B52(-12.225,-11.225) BE1(12.814,9.992) BE53(-12.814,9.992) BG1(12.814,10.773) BG53(-12.814,10.773) BH2(12.225,11.225) BH52(-12.225,11.225) BJ3(11.773,11.814) BJ5(10.992,11.814) BJ49(-10.992,11.814) BJ51(-11.773,11.814) C53(-12.814,-10.773) E1(12.814,-10.17) E53(-12.814,-9.992) F1(12.814,-9.447)
  round 0.356 smd: A7(9.748,-11.814) A9(8.836,-11.814) A47(-9.621,-11.814) A48(-10.294,-11.814) B4(11.632,-11.238) B5(11.038,-11.222) B6(10.445,-11.221) B8(9.258,-11.224) B46(-9.258,-11.224) B48(-10.445,-11.221) B49(-11.038,-11.222) B50(-11.632,-11.238) BC1(12.814,8.621) BC2(12.246,8.852) BC52(-12.246,8.852) BC53(-12.814,8.621) BD1(12.814,9.294) BD2(12.221,9.445) BD52(-12.221,9.445) BD53(-12.814,9.294) BE2(12.222,10.038) BE52(-12.222,10.038) BF2(12.238,10.632) BF52(-12.238,10.632) BG3(11.644,10.644) BG51(-11.644,10.644) BH4(11.632,11.238) BH5(11.038,11.222) BH6(10.445,11.221) BH8(9.258,11.224) BH46(-9.258,11.224) BH48(-10.445,11.221) BH49(-11.038,11.222) BH50(-11.632,11.238) BJ6(10.294,11.814) BJ7(9.621,11.814) BJ47(-9.621,11.814) BJ48(-10.294,11.814) C3(11.644,-10.644) C51(-11.644,-10.644) D2(12.238,-10.632) D52(-12.238,-10.632) E2(12.222,-10.038) E52(-12.222,-10.038) F2(12.221,-9.445) F52(-12.221,-9.445) F53(-12.814,-9.294) G1(12.814,-8.679) G2(12.246,-8.852) G52(-12.246,-8.852) G53(-12.814,-8.621) J1(12.814,-7.816)
  oval 0.254x0.343 smd: A11(7.774,-11.814) A13(6.803,-11.814) A15(5.831,-11.814) A17(4.859,-11.814) A19(3.887,-11.814) A21(2.915,-11.814) A23(1.944,-11.814) A25(0.972,-11.814) A27(0,-11.814) A29(-0.972,-11.814) A31(-1.944,-11.814) A33(-2.915,-11.814) A35(-3.887,-11.814) A37(-4.859,-11.814) A39(-5.831,-11.814) A41(-6.803,-11.814) A43(-7.774,-11.814) A45(-8.746,-11.814) BJ9(8.746,11.814) BJ11(7.774,11.814) BJ13(6.803,11.814) BJ15(5.831,11.814) BJ17(4.859,11.814) BJ19(3.887,11.814) BJ21(2.915,11.814) BJ23(1.944,11.814) BJ25(0.972,11.814) BJ27(0,11.814) BJ29(-0.972,11.814) BJ31(-1.944,11.814) BJ33(-2.915,11.814) BJ35(-3.887,11.814) BJ37(-4.859,11.814) BJ39(-5.831,11.814) BJ41(-6.803,11.814) BJ43(-7.774,11.814) BJ45(-8.746,11.814)
  oval 0.343x0.254 smd: AA1(12.814,-1.944) AA53(-12.814,-1.944) AC1(12.814,-0.972) AC53(-12.814,-0.972) AE1(12.814,0) AE53(-12.814,0) AG1(12.814,0.972) AG53(-12.814,0.972) AJ1(12.814,1.944) AJ53(-12.814,1.944) AL1(12.814,2.915) AL53(-12.814,2.915) AN1(12.814,3.887) AN53(-12.814,3.887) AR1(12.814,4.859) AR53(-12.814,4.859) AU1(12.814,5.831) AU53(-12.814,5.831) AW1(12.814,6.803) AW53(-12.814,6.803) BA1(12.814,7.774) BA53(-12.814,7.774) J53(-12.814,-7.774) L1(12.814,-6.803) L53(-12.814,-6.803) N1(12.814,-5.831) N53(-12.814,-5.831) R1(12.814,-4.859) R53(-12.814,-4.859) U1(12.814,-3.887) U53(-12.814,-3.887) W1(12.814,-2.915) W53(-12.814,-2.915)
  round 0.279 smd: AA3(12.071,-1.944) AA51(-12.071,-1.944) AB2(12.429,-1.458) AB3(11.73,-1.458) AB51(-11.73,-1.458) AB52(-12.429,-1.458) AC3(12.071,-0.972) AC51(-12.071,-0.972) AD2(12.429,-0.486) AD3(11.715,-0.48) AD51(-11.715,-0.48) AD52(-12.429,-0.486) AE3(12.071,0) AE4(11.366,0) AE50(-11.366,0) AE51(-12.071,0) AF2(12.429,0.486) AF3(11.715,0.48) AF51(-11.715,0.48) AF52(-12.429,0.486) AG3(12.071,0.972) AG51(-12.071,0.972) AH2(12.429,1.458) AH3(11.73,1.458) AH51(-11.73,1.458) AH52(-12.429,1.458) AJ3(12.071,1.944) AJ51(-12.071,1.944) AK2(12.429,2.43) AK3(11.73,2.43) AK51(-11.73,2.43) AK52(-12.429,2.43) AL3(12.071,2.915) AL51(-12.071,2.915) AM2(12.429,3.401) AM3(11.73,3.401) AM51(-11.73,3.401) AM52(-12.429,3.401) AN3(12.071,3.887) AN51(-12.071,3.887) AP2(12.429,4.373) AP3(11.73,4.373) AP51(-11.73,4.373) AP52(-12.429,4.373) AR3(12.071,4.859) AR51(-12.071,4.859) AT2(12.429,5.345) AT3(11.73,5.345) AT51(-11.73,5.345) AT52(-12.429,5.345) AU3(12.071,5.831) AU51(-12.071,5.831) AV2(12.429,6.317) AV3(11.73,6.317) AV51(-11.73,6.317) AV52(-12.429,6.317) AW3(12.071,6.803) AW51(-12.071,6.803) AY2(12.429,7.289) AY3(11.73,7.289) AY51(-11.73,7.289) AY52(-12.429,7.289) B10(8.26,-11.429) B12(7.289,-11.429) B14(6.317,-11.429) B16(5.345,-11.429) B18(4.373,-11.429) B20(3.401,-11.429) B22(2.43,-11.429) B24(1.458,-11.429) B26(0.486,-11.429) B28(-0.486,-11.429) B30(-1.458,-11.429) B32(-2.43,-11.429) B34(-3.401,-11.429) B36(-4.373,-11.429) B38(-5.345,-11.429) B40(-6.317,-11.429) B42(-7.289,-11.429) B44(-8.26,-11.429) BA3(12.071,7.774) BA51(-12.071,7.774) BB3(11.929,8.351) BB51(-11.929,8.351) BF27(0,10.366) BG9(8.698,11.028) BG11(7.774,11.071) BG12(7.289,10.73) BG13(6.803,11.071) BG14(6.317,10.73) BG15(5.831,11.071) BG16(5.345,10.73) BG17(4.859,11.071) BG18(4.373,10.73) BG19(3.887,11.071) BG20(3.401,10.73) BG21(2.915,11.071) BG22(2.43,10.73) BG23(1.944,11.071) BG24(1.458,10.73) BG25(0.972,11.071) BG26(0.48,10.715) BG27(0,11.071) BG28(-0.48,10.715) BG29(-0.972,11.071) BG30(-1.458,10.73) BG31(-1.944,11.071) BG32(-2.43,10.73) BG33(-2.915,11.071) BG34(-3.401,10.73) BG35(-3.887,11.071) BG36(-4.373,10.73) BG37(-4.859,11.071) BG38(-5.345,10.73) BG39(-5.831,11.071) BG40(-6.317,10.73) BG41(-6.803,11.071) BG42(-7.289,10.73) BG43(-7.774,11.071) BG45(-8.698,11.028) BH10(8.26,11.429) BH12(7.289,11.429) BH14(6.317,11.429) BH16(5.345,11.429) BH18(4.373,11.429) BH20(3.401,11.429) BH22(2.43,11.429) BH24(1.458,11.429) BH26(0.486,11.429) BH28(-0.486,11.429) BH30(-1.458,11.429) BH32(-2.43,11.429) BH34(-3.401,11.429) BH36(-4.373,11.429) BH38(-5.345,11.429) BH40(-6.317,11.429) BH42(-7.289,11.429) BH44(-8.26,11.429) C9(8.698,-11.028) C11(7.774,-11.071) C12(7.289,-10.73) C13(6.803,-11.071) C14(6.317,-10.73) C15(5.831,-11.071) C16(5.345,-10.73) C17(4.859,-11.071) C18(4.373,-10.73) C19(3.887,-11.071) C20(3.401,-10.73) C21(2.915,-11.071) C22(2.43,-10.73) C23(1.944,-11.071) C24(1.458,-10.73) C25(0.972,-11.071) C26(0.48,-10.715) C27(0,-11.071) C28(-0.48,-10.715) C29(-0.972,-11.071) C30(-1.458,-10.73) C31(-1.944,-11.071) C32(-2.43,-10.73) C33(-2.915,-11.071) C34(-3.401,-10.73) C35(-3.887,-11.071) C36(-4.373,-10.73) C37(-4.859,-11.071) C38(-5.345,-10.73) C39(-5.831,-11.071) C40(-6.317,-10.73) C41(-6.803,-11.071) C42(-7.289,-10.73) C43(-7.774,-11.071) C45(-8.698,-11.028) D27(0,-10.366) H3(11.929,-8.351) H51(-11.929,-8.351) J3(12.071,-7.774) J51(-12.071,-7.774) K2(12.429,-7.289) K3(11.73,-7.289) K51(-11.73,-7.289) K52(-12.429,-7.289) L3(12.071,-6.803) L51(-12.071,-6.803) M2(12.429,-6.317) M3(11.73,-6.317) M51(-11.73,-6.317) M52(-12.429,-6.317) N3(12.071,-5.831) N51(-12.071,-5.831) P2(12.429,-5.345) P3(11.73,-5.345) P51(-11.73,-5.345) P52(-12.429,-5.345) R3(12.071,-4.859) R51(-12.071,-4.859) T2(12.429,-4.373) T3(11.73,-4.373) T51(-11.73,-4.373) T52(-12.429,-4.373) U3(12.071,-3.887) U51(-12.071,-3.887) V2(12.429,-3.401) V3(11.73,-3.401) V51(-11.73,-3.401) V52(-12.429,-3.401) W3(12.071,-2.915) W51(-12.071,-2.915) Y2(12.429,-2.43) Y3(11.73,-2.43) Y51(-11.73,-2.43) Y52(-12.429,-2.43)
  round 0.33 smd: AA16(5.307,-1.961) AA18(4.549,-1.961) AA19(3.791,-1.961) AA21(3.033,-1.961) AA22(2.275,-1.961) AA24(1.516,-1.961) AA25(0.758,-1.961) AA27(0,-1.961) AA29(-0.758,-1.961) AA30(-1.516,-1.961) AA32(-2.275,-1.961) AA33(-3.033,-1.961) AA35(-3.791,-1.961) AA36(-4.549,-1.961) AA38(-5.307,-1.961) AC16(5.307,-1.177) AC18(4.549,-1.177) AC19(3.791,-1.177) AC21(3.033,-1.177) AC22(2.275,-1.177) AC24(1.516,-1.177) AC25(0.758,-1.177) AC27(0,-1.177) AC29(-0.758,-1.177) AC30(-1.516,-1.177) AC32(-2.275,-1.177) AC33(-3.033,-1.177) AC35(-3.791,-1.177) AC36(-4.549,-1.177) AC38(-5.307,-1.177) AD16(5.307,-0.392) AD18(4.549,-0.392) AD19(3.791,-0.392) AD21(3.033,-0.392) AD22(2.275,-0.392) AD24(1.516,-0.392) AD25(0.758,-0.392) AD27(0,-0.392) AD29(-0.758,-0.392) AD30(-1.516,-0.392) AD32(-2.275,-0.392) AD33(-3.033,-0.392) AD35(-3.791,-0.392) AD36(-4.549,-0.392) AD38(-5.307,-0.392) AF16(5.307,0.392) AF18(4.549,0.392) AF19(3.791,0.392) AF21(3.033,0.392) AF22(2.275,0.392) AF24(1.516,0.392) AF25(0.758,0.392) AF27(0,0.392) AF29(-0.758,0.392) AF30(-1.516,0.392) AF32(-2.275,0.392) AF33(-3.033,0.392) AF35(-3.791,0.392) AF36(-4.549,0.392) AF38(-5.307,0.392) AG16(5.307,1.177) AG18(4.549,1.177) AG19(3.791,1.177) AG21(3.033,1.177) AG22(2.275,1.177) AG24(1.516,1.177) AG25(0.758,1.177) AG27(0,1.177) AG29(-0.758,1.177) AG30(-1.516,1.177) AG32(-2.275,1.177) AG33(-3.033,1.177) AG35(-3.791,1.177) AG36(-4.549,1.177) AG38(-5.307,1.177) AJ16(5.307,1.961) AJ18(4.549,1.961) AJ19(3.791,1.961) AJ21(3.033,1.961) AJ22(2.275,1.961) AJ24(1.516,1.961) AJ25(0.758,1.961) AJ27(0,1.961) AJ29(-0.758,1.961) AJ30(-1.516,1.961) AJ32(-2.275,1.961) AJ33(-3.033,1.961) AJ35(-3.791,1.961) AJ36(-4.549,1.961) AJ38(-5.307,1.961) AK16(5.307,2.745) AK18(4.549,2.745) AK19(3.791,2.745) AK21(3.033,2.745) AK22(2.275,2.745) AK24(1.516,2.745) AK25(0.758,2.745) AK27(0,2.745) AK29(-0.758,2.745) AK30(-1.516,2.745) AK32(-2.275,2.745) AK33(-3.033,2.745) AK35(-3.791,2.745) AK36(-4.549,2.745) AK38(-5.307,2.745) AM16(5.307,3.53) AM18(4.549,3.53) AM19(3.791,3.53) AM21(3.033,3.53) AM22(2.275,3.53) AM24(1.516,3.53) AM25(0.758,3.53) AM27(0,3.53) AM29(-0.758,3.53) AM30(-1.516,3.53) AM32(-2.275,3.53) AM33(-3.033,3.53) AM35(-3.791,3.53) AM36(-4.549,3.53) AM38(-5.307,3.53) AN16(5.307,4.314) AN18(4.549,4.314) AN19(3.791,4.314) AN21(3.033,4.314) AN22(2.275,4.314) AN24(1.516,4.314) AN25(0.758,4.314) AN27(0,4.314) AN29(-0.758,4.314) AN30(-1.516,4.314) AN32(-2.275,4.314) AN33(-3.033,4.314) AN35(-3.791,4.314) AN36(-4.549,4.314) AN38(-5.307,4.314) U16(5.307,-4.314) U18(4.549,-4.314) U19(3.791,-4.314) U21(3.033,-4.314) U22(2.275,-4.314) U24(1.516,-4.314) U25(0.758,-4.314) U27(0,-4.314) U29(-0.758,-4.314) U30(-1.516,-4.314) U32(-2.275,-4.314) U33(-3.033,-4.314) U35(-3.791,-4.314) U36(-4.549,-4.314) U38(-5.307,-4.314) V16(5.307,-3.53) V18(4.549,-3.53) V19(3.791,-3.53) V21(3.033,-3.53) V22(2.275,-3.53) V24(1.516,-3.53) V25(0.758,-3.53) V27(0,-3.53) V29(-0.758,-3.53) V30(-1.516,-3.53) V32(-2.275,-3.53) V33(-3.033,-3.53) V35(-3.791,-3.53) V36(-4.549,-3.53) V38(-5.307,-3.53) Y16(5.307,-2.745) Y18(4.549,-2.745) Y19(3.791,-2.745) Y21(3.033,-2.745) Y22(2.275,-2.745) Y24(1.516,-2.745) Y25(0.758,-2.745) Y27(0,-2.745) Y29(-0.758,-2.745) Y30(-1.516,-2.745) Y32(-2.275,-2.745) Y33(-3.033,-2.745) Y35(-3.791,-2.745) Y36(-4.549,-2.745) Y38(-5.307,-2.745)
  round 0.305 smd: AB4(11.137,-1.448) AB6(10.463,-1.448) AB7(9.752,-1.448) AB9(9.041,-1.448) AB10(8.33,-1.448) AB12(7.618,-1.448) AB13(6.907,-1.448) AB14(6.196,-1.448) AB40(-6.196,-1.448) AB41(-6.907,-1.448) AB42(-7.618,-1.448) AB44(-8.33,-1.448) AB45(-9.041,-1.448) AB47(-9.752,-1.448) AB48(-10.463,-1.448) AB50(-11.137,-1.448) AD4(10.995,-0.463) AD6(10.404,-0.525) AD7(9.752,-0.475) AD9(9.041,-0.475) AD10(8.33,-0.475) AD12(7.618,-0.475) AD13(6.907,-0.475) AD14(6.196,-0.475) AD40(-6.196,-0.475) AD41(-6.907,-0.475) AD42(-7.618,-0.475) AD44(-8.33,-0.475) AD45(-9.041,-0.475) AD47(-9.752,-0.475) AD48(-10.404,-0.525) AD50(-10.995,-0.463) AE6(10.108,0) AE8(9.396,0) AE9(8.685,0) AE11(7.974,0) AE12(7.263,0) AE14(6.552,0) AE40(-6.552,0) AE42(-7.263,0) AE43(-7.974,0) AE45(-8.685,0) AE46(-9.396,0) AE48(-10.108,0) AF4(10.995,0.463) AF6(10.404,0.525) AF7(9.752,0.475) AF9(9.041,0.475) AF10(8.33,0.475) AF12(7.618,0.475) AF13(6.907,0.475) AF14(6.196,0.475) AF40(-6.196,0.475) AF41(-6.907,0.475) AF42(-7.618,0.475) AF44(-8.33,0.475) AF45(-9.041,0.475) AF47(-9.752,0.475) AF48(-10.404,0.525) AF50(-10.995,0.463) AH4(11.137,1.448) AH6(10.463,1.448) AH7(9.752,1.448) AH9(9.041,1.448) AH10(8.33,1.448) AH12(7.618,1.448) AH13(6.907,1.448) AH14(6.196,1.448) AH40(-6.196,1.448) AH41(-6.907,1.448) AH42(-7.618,1.448) AH44(-8.33,1.448) AH45(-9.041,1.448) AH47(-9.752,1.448) AH48(-10.463,1.448) AH50(-11.137,1.448) AK4(11.137,2.439) AK6(10.463,2.439) AK7(9.752,2.439) AK9(9.041,2.439) AK10(8.33,2.439) AK12(7.618,2.439) AK13(6.907,2.439) AK14(6.196,2.439) AK40(-6.196,2.439) AK41(-6.907,2.439) AK42(-7.618,2.439) AK44(-8.33,2.439) AK45(-9.041,2.439) AK47(-9.752,2.439) AK48(-10.463,2.439) AK50(-11.137,2.439) AM4(11.137,3.386) AM6(10.463,3.412) AM7(9.752,3.412) AM9(9.041,3.412) AM10(8.33,3.412) AM12(7.618,3.412) AM13(6.907,3.412) AM14(6.196,3.412) AM40(-6.196,3.412) AM41(-6.907,3.412) AM42(-7.618,3.412) AM44(-8.33,3.412) AM45(-9.041,3.412) AM47(-9.752,3.412) AM48(-10.463,3.412) AM50(-11.137,3.386) AN5(10.819,3.887) AN6(10.108,3.887) AN8(9.396,3.887) AN9(8.685,3.887) AN11(7.974,3.887) AN12(7.263,3.887) AN14(6.552,3.887) AN40(-6.552,3.887) AN42(-7.263,3.887) AN43(-7.974,3.887) AN45(-8.685,3.887) AN46(-9.396,3.887) AN48(-10.108,3.887) AN49(-10.819,3.887) AP4(11.137,4.388) AP6(10.463,4.362) AP7(9.752,4.362) AP9(9.041,4.362) AP10(8.33,4.362) AP12(7.618,4.362) AP13(6.907,4.362) AP14(6.196,4.362) AP40(-6.196,4.362) AP41(-6.907,4.362) AP42(-7.618,4.362) AP44(-8.33,4.362) AP45(-9.041,4.362) AP47(-9.752,4.362) AP48(-10.463,4.362) AP50(-11.137,4.388) AT4(11.137,5.336) AT6(10.463,5.336) AT7(9.752,5.336) AT9(9.041,5.336) AT10(8.33,5.336) AT12(7.618,5.336) AT13(6.907,5.336) AT14(6.305,5.336) AT16(5.336,5.196) AT18(4.362,5.196) AT19(3.887,5.552) AT20(3.412,5.196) AT22(2.439,5.196) AT24(1.448,5.196) AT26(0.475,5.196) AT27(0,5.552) AT28(-0.475,5.196) AT30(-1.448,5.196) AT32(-2.439,5.196) AT34(-3.412,5.196) AT35(-3.887,5.552) AT36(-4.362,5.196) AT38(-5.336,5.196) AT40(-6.305,5.336) AT41(-6.907,5.336) AT42(-7.618,5.336) AT44(-8.33,5.336) AT45(-9.041,5.336) AT47(-9.752,5.336) AT48(-10.463,5.336) AT50(-11.137,5.336) AU16(5.336,5.907) AU18(4.362,5.907) AU20(3.412,5.907) AU22(2.439,5.907) AU24(1.448,5.907) AU26(0.475,5.907) AU28(-0.475,5.907) AU30(-1.448,5.907) AU32(-2.439,5.907) AU34(-3.412,5.907) AU36(-4.362,5.907) AU38(-5.336,5.907) AV4(11.137,6.326) AV6(10.463,6.326) AV7(9.752,6.326) AV9(9.041,6.326) AV10(8.33,6.326) AV12(7.618,6.326) AV13(6.907,6.326) AV14(6.326,6.446) AV16(5.336,6.618) AV18(4.362,6.618) AV19(3.887,6.263) AV20(3.412,6.618) AV22(2.439,6.618) AV24(1.448,6.618) AV26(0.475,6.618) AV27(0,6.263) AV28(-0.475,6.618) AV30(-1.448,6.618) AV32(-2.439,6.618) AV34(-3.412,6.618) AV35(-3.887,6.263) AV36(-4.362,6.618) AV38(-5.336,6.618) AV40(-6.326,6.446) AV41(-6.907,6.326) AV42(-7.618,6.326) AV44(-8.33,6.326) AV45(-9.041,6.326) AV47(-9.752,6.326) AV48(-10.463,6.326) AV50(-11.137,6.326) AW13(6.751,6.915) AW19(3.887,6.974) AW27(0,6.974) AW35(-3.887,6.974) AW41(-6.751,6.915) AY4(11.137,7.317) AY6(10.463,7.317) AY7(9.752,7.317) AY9(9.041,7.317) AY10(8.33,7.317) AY12(7.317,7.34) AY14(6.326,7.33) AY16(5.336,7.33) AY18(4.362,7.33) AY20(3.412,7.33) AY22(2.439,7.33) AY24(1.448,7.33) AY26(0.475,7.33) AY28(-0.475,7.33) AY30(-1.448,7.33) AY32(-2.439,7.33) AY34(-3.412,7.33) AY36(-4.362,7.33) AY38(-5.336,7.33) AY40(-6.326,7.33) AY42(-7.317,7.34) AY44(-8.33,7.317) AY45(-9.041,7.317) AY47(-9.752,7.317) AY48(-10.463,7.317) AY50(-11.137,7.317) B7(9.852,-11.23) B47(-9.852,-11.23) BA12(7.317,8.041) BA14(6.326,8.041) BA16(5.336,8.041) BA18(4.362,8.041) BA19(3.887,7.685) BA20(3.412,8.041) BA22(2.439,8.041) BA24(1.448,8.041) BA26(0.475,8.041) BA27(0,7.685) BA28(-0.475,8.041) BA30(-1.448,8.041) BA32(-2.439,8.041) BA34(-3.412,8.041) BA35(-3.887,7.685) BA36(-4.362,8.041) BA38(-5.336,8.041) BA40(-6.326,8.041) BA42(-7.317,8.041) BB4(11.258,8.307) BB5(10.547,8.307) BB7(9.835,8.307) BB8(9.124,8.307) BB10(8.307,8.17) BB19(3.887,8.396) BB27(0,8.396) BB35(-3.887,8.396) BB44(-8.307,8.17) BB46(-9.124,8.307) BB47(-9.835,8.307) BB49(-10.547,8.307) BB50(-11.258,8.307) BC10(8.307,8.764) BC12(7.317,8.752) BC14(6.326,8.752) BC16(5.336,8.752) BC18(4.362,8.752) BC20(3.412,8.752) BC22(2.439,8.752) BC24(1.448,8.752) BC26(0.475,8.752) BC28(-0.475,8.752) BC30(-1.448,8.752) BC32(-2.439,8.752) BC34(-3.412,8.752) BC36(-4.362,8.752) BC38(-5.336,8.752) BC40(-6.326,8.752) BC42(-7.317,8.752) BC44(-8.307,8.764) BD5(10.565,9.302) BD7(9.712,9.302) BD10(8.307,9.457) BD12(7.317,9.463) BD14(6.326,9.463) BD16(5.336,9.463) BD18(4.362,9.463) BD19(3.887,9.108) BD20(3.412,9.463) BD22(2.439,9.463) BD24(1.448,9.463) BD26(0.525,9.404) BD27(0,9.108) BD28(-0.525,9.404) BD30(-1.448,9.463) BD32(-2.439,9.463) BD34(-3.412,9.463) BD35(-3.887,9.108) BD36(-4.362,9.463) BD38(-5.336,9.463) BD40(-6.326,9.463) BD42(-7.317,9.463) BD44(-8.307,9.457) BD47(-9.712,9.302) BD49(-10.565,9.302) BE3(11.643,9.58) BE8(9.32,9.747) BE19(3.887,9.819) BE35(-3.887,9.819) BE46(-9.32,9.747) BE51(-11.643,9.58) BF4(11.163,10.163) BF6(10.113,10.238) BF10(8.307,10.168) BF12(7.317,10.137) BF14(6.326,10.137) BF16(5.336,10.137) BF18(4.388,10.137) BF20(3.386,10.137) BF22(2.439,10.137) BF24(1.448,10.137) BF26(0.463,9.995) BF28(-0.463,9.995) BF30(-1.448,10.137) BF32(-2.439,10.137) BF34(-3.386,10.137) BF36(-4.388,10.137) BF38(-5.336,10.137) BF40(-6.326,10.137) BF42(-7.317,10.137) BF44(-8.307,10.168) BF48(-10.113,10.238) BF50(-11.163,10.163) BG5(10.58,10.643) BG7(9.553,10.709) BG47(-9.553,10.709) BG49(-10.58,10.643) BH7(9.852,11.23) BH47(-9.852,11.23) C5(10.58,-10.643) C7(9.553,-10.709) C47(-9.553,-10.709) C49(-10.58,-10.643) D4(11.163,-10.163) D6(10.113,-10.238) D10(8.307,-10.168) D12(7.317,-10.137) D14(6.326,-10.137) D16(5.336,-10.137) D18(4.388,-10.137) D20(3.386,-10.137) D22(2.439,-10.137) D24(1.448,-10.137) D26(0.463,-9.995) D28(-0.463,-9.995) D30(-1.448,-10.137) D32(-2.439,-10.137) D34(-3.386,-10.137) D36(-4.388,-10.137) D38(-5.336,-10.137) D40(-6.326,-10.137) D42(-7.317,-10.137) D44(-8.307,-10.168) D48(-10.113,-10.238) D50(-11.163,-10.163) E3(11.643,-9.58) E8(9.32,-9.747) E19(3.887,-9.819) E35(-3.887,-9.819) E46(-9.32,-9.747) E51(-11.643,-9.58) F5(10.565,-9.302) F7(9.712,-9.302) F10(8.307,-9.457) F12(7.317,-9.463) F14(6.326,-9.463) F16(5.336,-9.463) F18(4.362,-9.463) F19(3.887,-9.108) F20(3.412,-9.463) F22(2.439,-9.463) F24(1.448,-9.463) F26(0.525,-9.404) F27(0,-9.108) F28(-0.525,-9.404) F30(-1.448,-9.463) F32(-2.439,-9.463) F34(-3.412,-9.463) F35(-3.887,-9.108) F36(-4.362,-9.463) F38(-5.336,-9.463) F40(-6.326,-9.463) F42(-7.317,-9.463) F44(-8.307,-9.457) F47(-9.712,-9.302) F49(-10.565,-9.302) G10(8.307,-8.764) G12(7.317,-8.752) G14(6.326,-8.752) G16(5.336,-8.752) G18(4.362,-8.752) G20(3.412,-8.752) G22(2.439,-8.752) G24(1.448,-8.752) G26(0.475,-8.752) G28(-0.475,-8.752) G30(-1.448,-8.752) G32(-2.439,-8.752) G34(-3.412,-8.752) G36(-4.362,-8.752) G38(-5.336,-8.752) G40(-6.326,-8.752) G42(-7.317,-8.752) G44(-8.307,-8.764) H4(11.258,-8.307) H5(10.547,-8.307) H7(9.835,-8.307) H8(9.124,-8.307) H10(8.307,-8.17) H19(3.887,-8.396) H27(0,-8.396) H35(-3.887,-8.396) H44(-8.307,-8.17) H46(-9.124,-8.307) H47(-9.835,-8.307) H49(-10.547,-8.307) H50(-11.258,-8.307) J12(7.317,-8.041) J14(6.326,-8.041) J16(5.336,-8.041) J18(4.362,-8.041) J19(3.887,-7.685) J20(3.412,-8.041) J22(2.439,-8.041) J24(1.448,-8.041) J26(0.475,-8.041) J27(0,-7.685) J28(-0.475,-8.041) J30(-1.448,-8.041) J32(-2.439,-8.041) J34(-3.412,-8.041) J35(-3.887,-7.685) J36(-4.362,-8.041) J38(-5.336,-8.041) J40(-6.326,-8.041) J42(-7.317,-8.041) K4(11.137,-7.317) K6(10.463,-7.317) K7(9.752,-7.317) K9(9.041,-7.317) K10(8.33,-7.317) K12(7.317,-7.34) K14(6.326,-7.33) K16(5.336,-7.33) K18(4.362,-7.33) K20(3.412,-7.33) K22(2.439,-7.33) K24(1.448,-7.33) K26(0.475,-7.33) K28(-0.475,-7.33) K30(-1.448,-7.33) K32(-2.439,-7.33) K34(-3.412,-7.33) K36(-4.362,-7.33) K38(-5.336,-7.33) K40(-6.326,-7.33) K42(-7.317,-7.34) K44(-8.33,-7.317) K45(-9.041,-7.317) K47(-9.752,-7.317) K48(-10.463,-7.317) K50(-11.137,-7.317) L13(6.751,-6.915) L19(3.887,-6.974) L27(0,-6.974) L35(-3.887,-6.974) L41(-6.751,-6.915) M4(11.137,-6.326) M6(10.463,-6.326) M7(9.752,-6.326) M9(9.041,-6.326) M10(8.33,-6.326) M12(7.618,-6.326) M13(6.907,-6.326) M14(6.326,-6.446) M16(5.336,-6.618) M18(4.362,-6.618) M19(3.887,-6.263) M20(3.412,-6.618) M22(2.439,-6.618) M24(1.448,-6.618) M26(0.475,-6.618) M27(0,-6.263) M28(-0.475,-6.618) M30(-1.448,-6.618) M32(-2.439,-6.618) M34(-3.412,-6.618) M35(-3.887,-6.263) M36(-4.362,-6.618) M38(-5.336,-6.618) M40(-6.326,-6.446) M41(-6.907,-6.326) M42(-7.618,-6.326) M44(-8.33,-6.326) M45(-9.041,-6.326) M47(-9.752,-6.326) M48(-10.463,-6.326) M50(-11.137,-6.326) N16(5.336,-5.907) N18(4.362,-5.907) N20(3.412,-5.907) N22(2.439,-5.907) N24(1.448,-5.907) N26(0.475,-5.907) N28(-0.475,-5.907) N30(-1.448,-5.907) N32(-2.439,-5.907) N34(-3.412,-5.907) N36(-4.362,-5.907) N38(-5.336,-5.907) P4(11.137,-5.336) P6(10.463,-5.336) P7(9.752,-5.336) P9(9.041,-5.336) P10(8.33,-5.336) P12(7.618,-5.336) P13(6.907,-5.336) P14(6.305,-5.336) P16(5.336,-5.196) P18(4.362,-5.196) P19(3.887,-5.552) P20(3.412,-5.196) P22(2.439,-5.196) P24(1.448,-5.196) P26(0.475,-5.196) P27(0,-5.552) P28(-0.475,-5.196) P30(-1.448,-5.196) P32(-2.439,-5.196) P34(-3.412,-5.196) P35(-3.887,-5.552) P36(-4.362,-5.196) P38(-5.336,-5.196) P40(-6.305,-5.336) P41(-6.907,-5.336) P42(-7.618,-5.336) P44(-8.33,-5.336) P45(-9.041,-5.336) P47(-9.752,-5.336) P48(-10.463,-5.336) P50(-11.137,-5.336) T4(11.137,-4.388) T6(10.463,-4.362) T7(9.752,-4.362) T9(9.041,-4.362) T10(8.33,-4.362) T12(7.618,-4.362) T13(6.907,-4.362) T14(6.196,-4.362) T40(-6.196,-4.362) T41(-6.907,-4.362) T42(-7.618,-4.362) T44(-8.33,-4.362) T45(-9.041,-4.362) T47(-9.752,-4.362) T48(-10.463,-4.362) T50(-11.137,-4.388) U5(10.819,-3.887) U6(10.108,-3.887) U8(9.396,-3.887) U9(8.685,-3.887) U11(7.974,-3.887) U12(7.263,-3.887) U14(6.552,-3.887) U40(-6.552,-3.887) U42(-7.263,-3.887) U43(-7.974,-3.887) U45(-8.685,-3.887) U46(-9.396,-3.887) U48(-10.108,-3.887) U49(-10.819,-3.887) V4(11.137,-3.386) V6(10.463,-3.412) V7(9.752,-3.412) V9(9.041,-3.412) V10(8.33,-3.412) V12(7.618,-3.412) V13(6.907,-3.412) V14(6.196,-3.412) V40(-6.196,-3.412) V41(-6.907,-3.412) V42(-7.618,-3.412) V44(-8.33,-3.412) V45(-9.041,-3.412) V47(-9.752,-3.412) V48(-10.463,-3.412) V50(-11.137,-3.386) Y4(11.137,-2.439) Y6(10.463,-2.439) Y7(9.752,-2.439) Y9(9.041,-2.439) Y10(8.33,-2.439) Y12(7.618,-2.439) Y13(6.907,-2.439) Y14(6.196,-2.439) Y40(-6.196,-2.439) Y41(-6.907,-2.439) Y42(-7.618,-2.439) Y44(-8.33,-2.439) Y45(-9.041,-2.439) Y47(-9.752,-2.439) Y48(-10.463,-2.439) Y50(-11.137,-2.439)
C402-TO0D2H26
  custom 0.152x0.152 smd: 1(0,0.457) 2(0,-0.457)
C402-TO0D2H28
  custom 0.152x0.152 smd: 1(0,0.457) 2(0,-0.457)
C402H22
  custom 0.14x0.14 smd: 1(0,0.445) 2(0,-0.445)
C402H24
  custom 0.14x0.14 smd: 1(0,0.445) 2(0,-0.445)
C402H25
  custom 0.14x0.14 smd: 1(0,0.445) 2(0,-0.445)
C603
  custom 0.197x0.197 smd: 1(0,0.66) 2(0,-0.66)
C603H36
  custom 0.197x0.197 smd: 1(0,0.66) 2(0,-0.66)
C603H38
  custom 0.197x0.197 smd: 1(0,0.66) 2(0,-0.66)
C603H40
  custom 0.197x0.197 smd: 1(0,0.66) 2(0,-0.66)
C805H54
  rect 1.549x0.94 smd: 1(0,0.838) 2(0,-0.838)
C805H56
  rect 1.549x0.94 smd: 1(0,0.838) 2(0,-0.838)
C805H58
  rect 1.549x0.94 smd: 1(0,0.838) 2(0,-0.838)
CON2O-U
  custom 0.159x0.159 smd: 1(0,0.254) 2(0,-0.254)
CT3528H79
  rect 2.286x2.286 smd: 1(0,1.905) 2(0,-1.905)
CT7343H83
  rect 2.413x2.286 smd: 1(0,3.15) 2(0,-3.15)
DFN8F3-G2PH26
  rect 0.406x0.813 smd: 1(0.975,1.602) 2(0.325,1.602) 3(-0.325,1.602) 4(-0.975,1.602) 5(-0.975,-1.602) 6(-0.325,-1.602) 7(0.325,-1.602) 8(0.975,-1.602)
  rect 2.489x1.041 smd: 9(0,-0.41)
  rect 2.489x0.559 smd: 10(0,0.645)
DFN8G2-G1711H26
  rect 0.305x0.635 smd: 1(0.75,1.127) 2(0.25,1.127) 3(-0.25,1.127) 4(-0.75,1.127) 5(-0.75,-1.127) 6(-0.25,-1.127) 7(0.25,-1.127) 8(0.75,-1.127)
  rect 1.702x1.092 smd: 9(0,0)
DFN10G3-G265175H32
  rect 0.305x0.914 smd: 1(1,1.549) 2(0.5,1.549) 3(0,1.549) 4(-0.5,1.549) 5(-1,1.549) 6(-1,-1.549) 7(-0.5,-1.549) 8(0,-1.549) 9(0.5,-1.549) 10(1,-1.549)
  rect 2.642x1.753 smd: 11(0,0)
DFN10G2510H22
  rect 0.305x0.787 smd: 1(1,0.494) 5(-1,0.494) 6(-1,-0.494) 10(1,-0.494)
  rect 0.254x0.787 smd: 2(0.521,0.494) 4(-0.521,0.494) 7(-0.521,-0.494) 9(0.521,-0.494)
  rect 0.025x0.025 smd: 3(0,0.494)
  rect 0.406x1.753 smd: 8(0,-0.494)
DO214AAAKH97
  rect 2.261x1.905 smd: A(0,2.35) K(0,-2.35)
